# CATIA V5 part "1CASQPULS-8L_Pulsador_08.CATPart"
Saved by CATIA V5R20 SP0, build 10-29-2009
Part number: 1CASQPULS-8L_Pulsador_08
Revision: ANY
Definition: UNKNOWN
Nomenclature: 1CASQPULS-8L_Pulsador_08
Source: Unknown
Bounding box of the stored display mesh (mm): x -7.604 to 7.604, y 0 to 15.3, z -7.8 to 7.8
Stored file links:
  C:\Users\Utente\Desktop\IO LAVORO\3D X SITO CF\CUMSA\3D files AE\AE 082430\1CASQPULS-8L_Pulsador_08.CATPart
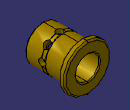
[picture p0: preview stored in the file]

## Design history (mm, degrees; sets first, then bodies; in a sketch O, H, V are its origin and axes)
Body1 "MatrizC1" (main body)
  Solid1: solid without history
